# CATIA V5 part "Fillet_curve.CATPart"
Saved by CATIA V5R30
Part number: Part1
Bounding box of the stored display mesh (mm): x -44.747 to 47.153, y -50.22 to 55.347, z 0 to 0
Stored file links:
  D:\PROJECTS\CATIA V56R 2020\Resources\Parts File\c17_catia_v6_6r2020_prt\Fillet_curve.CATPart
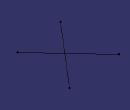
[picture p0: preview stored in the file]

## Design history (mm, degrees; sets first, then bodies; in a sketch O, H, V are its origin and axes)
Body1 (main body)
  Sketch1 on xy-plane, origin (0, 0, 0), H (1, 0, 0), V (0, 1, 0)
    line L1 (-44.7471, 47.4214) -> (39.0352, -41.3682)
    coincidence: L1 O
  Sketch2 on xy-plane, origin (0, 0, 0), H (1, 0, 0), V (0, 1, 0)
    line L1 (47.1532, 55.3475) -> (-42.7846, -50.2197)
    coincidence: L1 O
